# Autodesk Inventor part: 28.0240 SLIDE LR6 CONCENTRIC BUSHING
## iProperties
Created: 2012-04
Part Number: 28.0240 SLIDE LR6 CONCENTRIC BUSHING
Document SubType Name: Modeling
Designer: Administrator
Density: 8.08 g/cm^3
Material: Stainless Steel
Mass: 12.6858 g
Surface Area: 9.50526 cm^2
Volume: 1.57003 cm^3
Translation Standard: STEP AP214IS
FileName: C:\Documents and Settings\Administrator\My Documents\AAAAINTERNET\DOWNLOAD\LR6 BOLT HEAD.stp
PreProcessor: Autodesk Inventor 2009
PostProcessor: Build: 236a, Release: 2009 RTM - Date: Fri 02/22/2008
Sent Units: MM
Uncertainty: 0.01
Author: Administrator
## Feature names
1. Base1
2. Extrusion1
3. Chamfer1
